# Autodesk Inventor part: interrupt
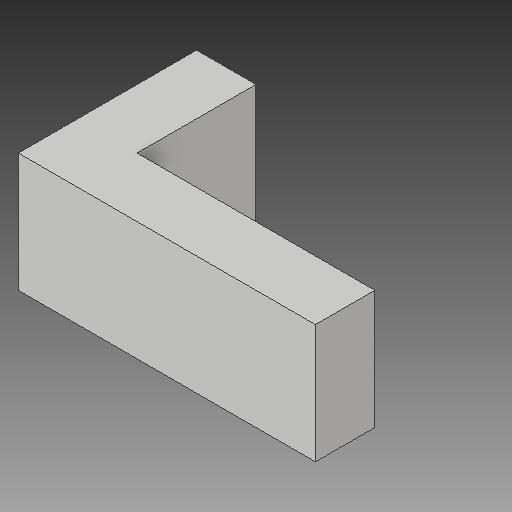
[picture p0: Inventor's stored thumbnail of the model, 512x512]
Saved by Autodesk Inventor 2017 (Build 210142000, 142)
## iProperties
Created: 2020-03
Part Number: interrupt
Material: Generic
Document SubType Name: Modeling
Designer: user
Density: 1 g/cm^3
Appearance: Default
Mass: 0.014 g
Surface Area: 0.46 cm^2
Volume: 0.014 cm^3
Author: user
Revision Number: ANY
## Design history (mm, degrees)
feature "Boss-Extrude1"
body "Solid1"
